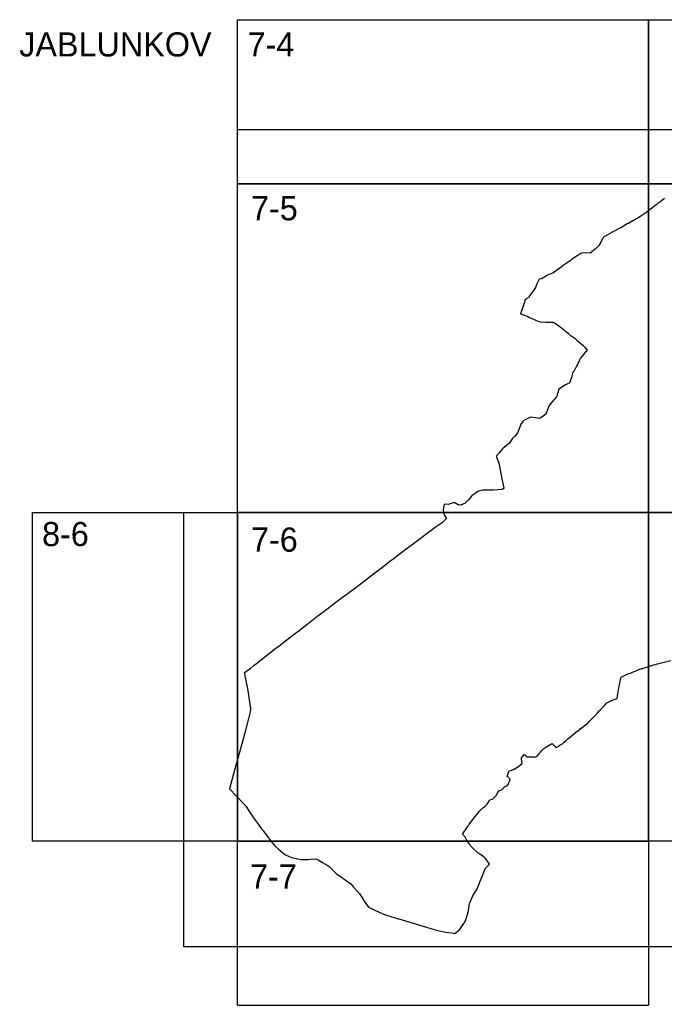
# Model space of a CAD drawing. Extents: x -447352 to -425530, y -1135906 to -1121091.
# Drawn here: x -435162.8 to -434917.6, y -1126653.4 to -1126278.4 of the extents above; entities that cross this region are included whole.
import ezdxf

# ---------------------------------------------------------------- set-up
doc = ezdxf.new("R2010")
doc.units = 0
for name, color, linetype in [('Vrstva 1', 7, 'Continuous'), ('Vrstva 10', 7, 'Continuous'), ('Vrstva 4', 7, 'Continuous')]:
    doc.layers.add(name, color=color, linetype=linetype)

msp = doc.modelspace()

# ---------------------------------------------------------------- linework, layer by layer
at = {"layer": 'Vrstva 1'}
for points in [[(-434917.58, -1126346.44), (-434918.79, -1126347.4), (-434918.79, -1126347.4), (-434919.94, -1126348.27), (-434920.51, -1126348.7), (-434921.09, -1126349.14), (-434921.25, -1126349.26), (-434923.38, -1126350.9), (-434924.45, -1126351.72), (-434924.92, -1126352.06), (-434925.68, -1126352.57), (-434925.93, -1126352.73), (-434926.52, -1126353.12), (-434926.56, -1126353.15), (-434926.77, -1126353.29), (-434927.68, -1126353.89), (-434927.69, -1126353.89), (-434928.16, -1126354.15), (-434928.31, -1126354.23), (-434928.49, -1126354.33), (-434928.95, -1126354.58), (-434929.13, -1126354.69), (-434929.29, -1126354.78), (-434929.39, -1126354.84), (-434929.63, -1126354.98), (-434931.29, -1126355.92), (-434931.46, -1126356.01), (-434931.69, -1126356.14), (-434934.16, -1126357.54), (-434934.28, -1126357.61), (-434936.39, -1126358.74), (-434937.41, -1126359.29), (-434940.75, -1126361.1), (-434940.92, -1126361.4), (-434940.98, -1126361.51), (-434941.76, -1126362.97), (-434942.44, -1126364.29), (-434942.58, -1126364.42), (-434942.67, -1126364.5), (-434943.81, -1126365.54), (-434945.32, -1126366.92), (-434945.49, -1126367.07), (-434945.49, -1126367.08), (-434945.96, -1126367.09), (-434949.15, -1126367.18), (-434949.16, -1126367.18), (-434949.59, -1126367.47), (-434950.42, -1126368.04), (-434952.89, -1126369.7), (-434952.93, -1126369.72), (-434953.17, -1126369.9), (-434953.44, -1126370.1), (-434956.42, -1126372.23), (-434956.49, -1126372.28), (-434959.49, -1126374.46), (-434959.96, -1126374.8), (-434960.12, -1126374.86), (-434962.06, -1126375.58), (-434962.07, -1126375.58), (-434962.46, -1126375.82), (-434964.34, -1126376.98), (-434965.26, -1126377.19), (-434965.51, -1126377.7), (-434966.27, -1126379.21), (-434966.28, -1126379.22), (-434966.35, -1126379.48), (-434966.55, -1126380.32), (-434967.38, -1126381.43), (-434968.75, -1126383.38), (-434969.31, -1126384.19), (-434969.34, -1126384.21), (-434970.5, -1126384.85), (-434970.6, -1126384.91), (-434970.67, -1126385.3), (-434970.82, -1126386.11), (-434970.87, -1126386.3), (-434972.16, -1126389.88), (-434972.33, -1126390.36), (-434972.3, -1126390.35), (-434972.28, -1126390.34), (-434971.6, -1126390.6), (-434969.79, -1126391.26), (-434969.17, -1126391.55), (-434966.88, -1126392.63), (-434966.86, -1126392.63), (-434965.7, -1126393.1), (-434965.23, -1126393.28), (-434965.2, -1126393.29), (-434964.77, -1126393.32), (-434964.63, -1126393.33), (-434964.41, -1126393.35), (-434962.81, -1126393.45), (-434961.77, -1126393.52), (-434960.72, -1126393.49), (-434959.88, -1126393.46), (-434959.87, -1126393.46), (-434959.59, -1126393.61), (-434959.22, -1126393.87), (-434958.67, -1126394.25), (-434958.28, -1126394.53), (-434956.72, -1126395.67), (-434956.55, -1126395.79), (-434955.44, -1126396.71), (-434955.05, -1126397.03), (-434954.87, -1126397.18), (-434954.12, -1126397.79), (-434953.85, -1126398.02), (-434953.25, -1126398.51), (-434953.03, -1126398.69), (-434952.39, -1126399.11), (-434951.64, -1126399.61), (-434951.61, -1126399.63), (-434950.85, -1126400.31), (-434949.97, -1126401.09), (-434949.53, -1126401.47), (-434948.52, -1126402.36), (-434948.26, -1126402.59), (-434948.21, -1126402.64), (-434948.11, -1126402.74), (-434948.1, -1126402.75), (-434948.01, -1126402.85), (-434947.98, -1126402.88), (-434946.93, -1126404.11), (-434946.94, -1126404.12), (-434947.38, -1126404.61), (-434947.44, -1126404.68), (-434948.01, -1126405.31), (-434948.83, -1126406.37), (-434949, -1126406.58), (-434949.56, -1126407.3), (-434949.86, -1126407.83), (-434949.88, -1126407.87), (-434949.89, -1126407.89), (-434950.02, -1126408.17), (-434950.82, -1126409.84), (-434951.13, -1126410.48), (-434951.75, -1126411.77), (-434951.86, -1126412.01), (-434951.87, -1126412.01), (-434951.91, -1126412.04), (-434952.2, -1126412.24), (-434952.28, -1126412.28), (-434952.33, -1126412.38), (-434952.42, -1126412.58), (-434952.51, -1126412.86), (-434952.68, -1126413.42), (-434952.69, -1126413.44), (-434952.81, -1126413.94), (-434952.83, -1126414.01), (-434952.82, -1126414.07), (-434952.81, -1126414.15), (-434952.81, -1126414.22), (-434952.82, -1126414.27), (-434953.7, -1126416.6), (-434953.72, -1126416.65), (-434953.74, -1126416.69), (-434953.75, -1126416.7), (-434954.45, -1126417), (-434954.7, -1126417.11), (-434955.17, -1126417.35), (-434957.78, -1126419.04), (-434957.78, -1126419.04), (-434958.15, -1126420.35), (-434958.23, -1126420.61), (-434958.34, -1126421.03), (-434958.4, -1126421.24), (-434958.4, -1126421.25), (-434958.39, -1126421.25), (-434958.22, -1126421.41), (-434958.23, -1126421.42), (-434958.59, -1126421.81), (-434959.39, -1126422.81), (-434959.4, -1126422.82), (-434959.61, -1126423.07), (-434959.61, -1126423.08), (-434959.73, -1126423.23), (-434960.89, -1126424.58), (-434961.43, -1126425.21), (-434962.19, -1126427.16), (-434962.57, -1126428.18), (-434962.7, -1126428.53), (-434964.23, -1126429.63), (-434964.85, -1126430.07), (-434965.03, -1126430.11), (-434965.05, -1126430.11), (-434965.68, -1126430.02), (-434968.52, -1126429.6), (-434969.01, -1126429.84), (-434970.34, -1126430.48), (-434970.88, -1126430.74), (-434970.91, -1126430.77), (-434971.34, -1126431.18), (-434971.51, -1126431.4), (-434972.17, -1126432.25), (-434972.17, -1126432.26), (-434972.84, -1126434.06), (-434973.41, -1126435.56), (-434973.41, -1126435.56), (-434973.55, -1126435.78), (-434973.88, -1126436.15), (-434974.6, -1126436.95), (-434975.3, -1126437.72), (-434975.31, -1126437.74), (-434975.44, -1126437.93), (-434976.51, -1126439.5), (-434976.98, -1126439.88), (-434978.55, -1126441.14), (-434979.22, -1126441.68), (-434979.32, -1126441.76), (-434979.35, -1126441.8), (-434980.47, -1126443.23), (-434981.61, -1126444.54), (-434981.46, -1126444.71), (-434981.45, -1126444.74), (-434981.45, -1126444.75), (-434980.44, -1126447.51), (-434980.16, -1126449.17), (-434979.84, -1126451.12), (-434979.43, -1126453.08), (-434978.7, -1126456.58), (-434978.66, -1126456.78), (-434979.31, -1126457.12), (-434979.43, -1126457.19), (-434982.6, -1126457.45), (-434982.76, -1126457.45), (-434984.25, -1126457.42), (-434986.64, -1126457.4), (-434987.92, -1126457.67), (-434988.52, -1126457.94), (-434989.5, -1126458.74), (-434990.8, -1126459.61), (-434990.89, -1126459.72), (-434992.05, -1126461.14), (-434993.5, -1126462.48), (-434994.19, -1126462.8), (-434994.79, -1126463.08), (-434995.96, -1126463.01), (-434997.57, -1126462.16), (-434999.81, -1126462.83), (-435001.29, -1126462.8), (-435001.67, -1126464.91), (-435001.68, -1126464.93), (-435001.69, -1126465.02), (-435001.4, -1126466.83), (-435000.43, -1126468.15), (-435000.42, -1126468.17), (-435001.16, -1126468.92), (-435001.77, -1126469.48), (-435002.02, -1126469.71), (-435002.82, -1126470.34), (-435004.75, -1126471.57), (-435004.81, -1126471.61), (-435006.78, -1126473.14), (-435006.84, -1126473.18), (-435007.33, -1126473.56), (-435011.99, -1126477.02), (-435012.02, -1126477.05), (-435016.97, -1126480.81), (-435021.23, -1126484.06), (-435022.11, -1126484.72), (-435024.68, -1126486.66), (-435028.68, -1126489.79), (-435031.12, -1126491.66), (-435034.43, -1126494.19), (-435034.48, -1126494.23), (-435039.27, -1126497.74), (-435039.5, -1126497.92), (-435043.11, -1126500.6), (-435045.5, -1126502.42), (-435047.47, -1126503.9), (-435049.79, -1126505.65), (-435050.02, -1126505.82), (-435051.15, -1126506.71), (-435055.97, -1126510.51), (-435059.86, -1126513.46), (-435064.08, -1126516.71), (-435065.37, -1126517.71), (-435067.76, -1126519.59), (-435068.94, -1126520.51), (-435072.88, -1126523.56), (-435073.81, -1126524.27), (-435075.05, -1126525.23), (-435077.37, -1126527.03), (-435077.37, -1126527.03), (-435077.33, -1126527.21), (-435077.04, -1126528.59), (-435077.01, -1126528.75), (-435076.48, -1126531.29), (-435076.32, -1126532.02), (-435076.32, -1126532.06), (-435075.39, -1126537.94), (-435075.38, -1126537.97), (-435075.08, -1126539.7), (-435075.08, -1126539.72), (-435075.02, -1126540.09), (-435074.96, -1126540.51), (-435074.99, -1126540.88), (-435075.14, -1126541.61), (-435075.52, -1126543.4), (-435075.81, -1126544.58), (-435075.83, -1126544.63), (-435076.94, -1126548.8), (-435079.04, -1126556.68), (-435081.03, -1126563.9), (-435082.96, -1126571), (-435082.97, -1126571.04), (-435077.69, -1126576.64), (-435076.64, -1126577.77), (-435075.88, -1126578.99), (-435073.86, -1126582.05), (-435073.81, -1126582.12), (-435072.8, -1126583.53), (-435072.64, -1126583.74), (-435070.76, -1126586.22), (-435070.19, -1126586.96), (-435070.16, -1126587), (-435069.64, -1126587.72), (-435068.26, -1126589.62), (-435067.93, -1126590.07), (-435065.78, -1126592.79), (-435064.38, -1126594.01), (-435061.98, -1126595.99), (-435060.24, -1126596.74), (-435059.05, -1126597.26), (-435058.92, -1126597.31), (-435057.59, -1126597.59), (-435057.45, -1126597.62), (-435055.83, -1126597.95), (-435055.8, -1126597.95), (-435054.84, -1126597.93), (-435054.46, -1126597.93), (-435053.94, -1126597.92), (-435053.26, -1126597.91), (-435052.35, -1126597.87), (-435050.4, -1126597.71), (-435049.95, -1126597.78), (-435049.29, -1126598.13), (-435047.57, -1126599.08), (-435045.61, -1126600.18), (-435045.09, -1126600.66), (-435044.37, -1126601.34), (-435043.57, -1126602.09), (-435042.25, -1126603.39), (-435042.11, -1126603.49), (-435040.92, -1126604.34), (-435038.51, -1126606.05), (-435036.87, -1126607.23), (-435035.82, -1126608.41), (-435034.18, -1126610.23), (-435033.54, -1126610.94), (-435033.18, -1126611.53), (-435032.72, -1126612.27), (-435031.78, -1126613.74), (-435031.15, -1126614.66), (-435030.11, -1126616.1), (-435029.04, -1126616.61), (-435027.66, -1126617.26), (-435026.35, -1126617.87), (-435024.38, -1126618.76), (-435023.25, -1126619.11), (-435021.53, -1126619.68), (-435021.38, -1126619.73), (-435020.29, -1126620.05), (-435018.87, -1126620.47), (-435018.86, -1126620.47), (-435018.65, -1126620.53), (-435018.59, -1126620.55), (-435017.73, -1126620.81), (-435015.34, -1126621.5), (-435015.22, -1126621.54), (-435014.74, -1126621.68), (-435011.81, -1126622.55), (-435009.12, -1126623.38), (-435008.78, -1126623.48), (-435008.02, -1126623.71), (-435006.01, -1126624.33), (-435004.28, -1126624.88), (-435000.82, -1126625.62)], [(-435000.82, -1126625.62), (-434998.43, -1126625.81), (-434997.23, -1126626.04), (-434997.12, -1126625.95), (-434995.54, -1126624.68), (-434994.51, -1126623.2), (-434994.4, -1126623.05), (-434993.88, -1126622.29), (-434993.77, -1126622.12), (-434993.63, -1126621.89), (-434993.25, -1126621.26), (-434992.98, -1126620.43), (-434992.96, -1126620.36), (-434992.94, -1126620.31), (-434992.91, -1126620.2), (-434992.88, -1126620.11), (-434992.88, -1126620.1), (-434992.25, -1126617.9), (-434992.11, -1126617.38), (-434991.66, -1126614.63), (-434991.66, -1126614.63), (-434991.47, -1126614.19), (-434991.21, -1126613.57), (-434990.42, -1126611.74), (-434988.85, -1126609.09), (-434987.1, -1126604.96), (-434986.78, -1126604.32), (-434986.74, -1126604.19), (-434986.35, -1126603.09), (-434985.76, -1126601.42), (-434984.08, -1126599.71), (-434985.01, -1126598.47), (-434985.07, -1126598.38), (-434985.12, -1126598.32), (-434985.15, -1126598.28), (-434985.22, -1126598.18), (-434985.27, -1126598.1), (-434985.35, -1126597.98), (-434985.71, -1126597.46), (-434986.08, -1126597), (-434986.65, -1126596.63), (-434986.75, -1126596.57), (-434988.4, -1126595.5), (-434990.59, -1126593.56), (-434990.72, -1126593.39), (-434990.75, -1126593.35), (-434990.83, -1126593.25), (-434991.17, -1126592.83), (-434991.5, -1126592.42), (-434991.76, -1126592.1), (-434992.24, -1126591.51), (-434992.32, -1126591.41), (-434992.82, -1126590.45), (-434993.11, -1126589.89), (-434993.34, -1126589.46), (-434993.39, -1126589.37), (-434993.43, -1126589.32), (-434993.69, -1126589.03), (-434993.89, -1126588.8), (-434994.15, -1126588.51), (-434994.37, -1126588.26), (-434992.51, -1126585.52), (-434992.42, -1126585.4), (-434992.1, -1126584.95), (-434991.78, -1126584.51), (-434990.45, -1126582.68), (-434987.77, -1126579.42), (-434987.42, -1126579.1), (-434986.71, -1126578.4), (-434986.6, -1126578.31), (-434986.41, -1126578.17), (-434985.81, -1126577.69), (-434984.95, -1126576.85), (-434984.54, -1126576.09), (-434984.07, -1126575.22), (-434983.02, -1126574.98), (-434981.62, -1126573.55), (-434981.08, -1126572.7), (-434981.07, -1126572.69), (-434981.07, -1126572.67), (-434980.86, -1126572.34), (-434980.81, -1126572.26), (-434980.57, -1126571.87), (-434979.41, -1126571.43), (-434978.39, -1126570.25), (-434977.86, -1126570.05), (-434977.74, -1126570), (-434977.32, -1126569.84), (-434977.1, -1126569.45), (-434977.05, -1126569.36), (-434976.88, -1126569.06), (-434976.47, -1126568.32), (-434976.27, -1126567.41), (-434976.27, -1126567.39), (-434976.26, -1126567.38), (-434977.31, -1126566.39), (-434977.33, -1126566.38), (-434977.34, -1126566.36), (-434977.39, -1126566.32), (-434976.74, -1126564.52), (-434976.67, -1126564.32), (-434976.51, -1126564.26), (-434975.78, -1126563.97), (-434975.09, -1126563.7), (-434974.97, -1126563.65), (-434973.76, -1126562.94), (-434973.64, -1126562.86), (-434973.64, -1126562.86), (-434973.63, -1126562.85), (-434973.51, -1126562.78), (-434971.65, -1126561.38), (-434971.65, -1126561.34), (-434971.68, -1126561.18), (-434971.75, -1126560.7), (-434971.81, -1126560.35), (-434971.91, -1126559.73), (-434971.93, -1126559.62), (-434971.95, -1126559.49), (-434971.97, -1126559.32), (-434972, -1126559.18), (-434971.46, -1126558.62), (-434970.9, -1126558.05), (-434970.86, -1126558), (-434970.72, -1126558.1), (-434969.72, -1126558.89), (-434969.04, -1126558.9), (-434968.98, -1126558.9), (-434968.73, -1126558.91), (-434968.57, -1126558.91), (-434967.26, -1126558.93), (-434966.63, -1126558.95), (-434966.36, -1126558.79), (-434966.33, -1126558.77), (-434966.21, -1126558.7), (-434966.07, -1126558.61), (-434966.03, -1126558.58), (-434965.49, -1126557.98), (-434965.38, -1126557.86), (-434965.29, -1126557.76), (-434965.12, -1126557.58), (-434965.04, -1126557.49), (-434964.93, -1126557.37), (-434964.9, -1126557.33), (-434964.87, -1126557.3), (-434964.82, -1126557.24), (-434964.73, -1126557.13), (-434964.33, -1126556.63), (-434964.12, -1126556.37), (-434963.87, -1126556.05), (-434963.76, -1126555.97), (-434962.3, -1126554.9), (-434962.09, -1126554.77), (-434960.73, -1126554), (-434960.33, -1126553.77), (-434960.33, -1126553.77), (-434960.19, -1126553.92), (-434959.48, -1126554.63), (-434959.11, -1126555.01), (-434958.93, -1126555.18), (-434958.78, -1126555.33), (-434958.69, -1126555.29), (-434957.41, -1126554.52), (-434957.32, -1126554.47), (-434956.39, -1126553.91), (-434956.35, -1126553.88), (-434956.02, -1126553.59), (-434955.97, -1126553.55), (-434955.8, -1126553.4), (-434955.79, -1126553.39), (-434955.79, -1126553.39), (-434955.75, -1126553.35), (-434955.71, -1126553.31), (-434954.82, -1126552.5), (-434954.8, -1126552.49), (-434954.21, -1126551.95), (-434954.1, -1126551.86), (-434953.99, -1126551.76), (-434953.99, -1126551.76), (-434953.98, -1126551.76), (-434953.98, -1126551.76), (-434953.98, -1126551.75), (-434953.97, -1126551.75), (-434953.96, -1126551.74), (-434953.96, -1126551.74), (-434953.95, -1126551.73), (-434953.95, -1126551.73), (-434953.94, -1126551.73), (-434953.94, -1126551.73), (-434953.36, -1126551.24), (-434951.37, -1126549.56), (-434950.17, -1126548.71), (-434950.05, -1126548.63), (-434950, -1126548.59), (-434949.98, -1126548.58), (-434949.93, -1126548.55), (-434949.57, -1126548.28), (-434948.33, -1126547.34), (-434948.15, -1126547.2), (-434947.94, -1126547.04), (-434947.92, -1126547.02), (-434947.04, -1126546.35), (-434946.69, -1126546.08), (-434946.64, -1126546.02), (-434946.55, -1126545.92), (-434945.91, -1126545.24), (-434945.01, -1126544.26), (-434943.65, -1126542.85), (-434943.43, -1126542.62), (-434943.18, -1126542.34), (-434942.34, -1126541.39), (-434942.05, -1126541.07), (-434941.85, -1126540.86), (-434941.56, -1126540.54), (-434940.38, -1126539.35), (-434939.45, -1126538.33), (-434937.39, -1126537.32), (-434937.23, -1126537.27), (-434937.03, -1126537.19), (-434935.59, -1126536.7), (-434935.44, -1126535.83), (-434935.28, -1126534.96), (-434934.86, -1126532.59), (-434934.78, -1126532.12), (-434934.45, -1126530.24), (-434934.25, -1126529.36), (-434934.22, -1126529.24), (-434934.17, -1126529.05), (-434934.16, -1126529.01), (-434934.14, -1126528.94), (-434934.13, -1126528.9), (-434934.12, -1126528.85), (-434934.11, -1126528.81), (-434934.1, -1126528.79), (-434934.04, -1126528.58), (-434932.96, -1126528.04), (-434932.67, -1126527.9), (-434932.65, -1126527.89), (-434932.4, -1126527.76), (-434932.35, -1126527.74), (-434930.58, -1126527.02), (-434930.55, -1126527.01), (-434930.52, -1126526.99), (-434929.72, -1126526.68), (-434928.76, -1126526.28), (-434927.95, -1126525.94), (-434927.01, -1126525.55), (-434926.93, -1126525.52), (-434926.32, -1126525.28), (-434926.47, -1126525.44), (-434926.23, -1126525.35), (-434925.74, -1126525.15), (-434925.21, -1126524.99), (-434923.51, -1126524.47), (-434922.92, -1126524.3), (-434922.47, -1126524.18), (-434921.58, -1126523.93), (-434920.27, -1126523.55), (-434918.73, -1126523.09), (-434915.19, -1126522.22)]]:
    msp.add_lwpolyline(points, dxfattribs=at)
at = {"layer": 'Vrstva 10'}
msp.add_lwpolyline([(-434767.43, -1126320.23), (-434767.43, -1126631.21), (-435100.3, -1126631.21), (-435100.3, -1126465.91), (-435079.93, -1126465.91), (-435079.93, -1126340.91), (-435079.93, -1126320.23), (-434767.43, -1126320.23)], dxfattribs=at)
at = {"layer": 'Vrstva 4'}
for p, q in [((-435079.93, -1126278.41), (-434767.43, -1126278.41)), ((-435158.06, -1126465.91), (-435158.06, -1126590.91)), ((-435079.93, -1126653.41), (-434923.68, -1126653.41))]:
    msp.add_line(p, q, dxfattribs=at)
for points in [[(-434923.68, -1126278.41), (-434923.68, -1126340.91), (-435079.93, -1126340.91), (-435079.93, -1126278.41)], [(-434767.43, -1126278.41), (-434767.43, -1126340.91), (-434923.68, -1126340.91), (-434923.68, -1126278.41)], [(-435158.06, -1126465.91), (-435079.93, -1126465.91), (-435079.93, -1126590.91), (-435158.06, -1126590.91)], [(-435079.93, -1126653.41), (-435079.93, -1126590.91), (-434923.68, -1126590.91), (-434923.68, -1126653.41)]]:
    msp.add_lwpolyline(points, dxfattribs=at)
for points in [[(-434923.68, -1126340.91), (-434923.68, -1126465.91), (-435079.93, -1126465.91), (-435079.93, -1126340.91)], [(-434767.43, -1126340.91), (-434767.43, -1126465.91), (-434923.68, -1126465.91), (-434923.68, -1126340.91)], [(-434923.68, -1126465.91), (-434923.68, -1126590.91), (-435079.93, -1126590.91), (-435079.93, -1126465.91)], [(-434767.43, -1126465.91), (-434767.43, -1126590.91), (-434923.68, -1126590.91), (-434923.68, -1126465.91)]]:
    msp.add_lwpolyline(points, close=True, dxfattribs=at)

# ---------------------------------------------------------------- texts
at = {"layer": 'Vrstva 1'}
for s, p in [('JABLUNKOV', (-435162.97, -1126292.41)), ('7-4', (-435076.12, -1126292.41)), ('7-5', (-435074.81, -1126354.75)), ('8-6', (-435154.28, -1126478.72)), ('7-6', (-435074.81, -1126480.82)), ('7-7', (-435075.17, -1126608.99))]:
    msp.add_text(s, height=9.2, dxfattribs=at).set_placement(p)

doc.saveas('drawing.dxf')
